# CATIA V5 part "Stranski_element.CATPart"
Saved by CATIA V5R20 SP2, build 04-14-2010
Part number: Stranski_element
Bounding box of the stored display mesh (mm): x -125 to 100, y -20 to 30, z 0 to 2
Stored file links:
  C:\Documents and Settings\Administrator\My Documents\Hobi_dokumenti\CAD_CNC\Clap_CATIA\Stranski_element.CATPart
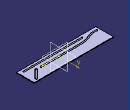
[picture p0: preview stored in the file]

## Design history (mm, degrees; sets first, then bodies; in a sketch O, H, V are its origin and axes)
Body1 (main body)
  Sketch1 on xy-plane, origin (0, 0, 0), H (1, 0, 0), V (0, 1, 0)
    line L1 (-125, 30) -> (100, 30)
    line L2 (100, 30) -> (100, -20)
    line L3 (100, -20) -> (-125, -20)
    line L4 (-125, -20) -> (-125, 30)
    distance V L4 = 125
    length L2 = 50
    distance V L2 = 100
    distance H L3 = 20
    horizontal: L1 H, L3 H
    vertical: L2 V, L4 V
  Pad1: profile Sketch1, direction (0, 0, 1), length 2
  Sketch2 on end face of Pad1, origin (0, 0, 2), H (1, 0, 0), V (0, 1, 0)
    arc A1 centre (87, 23) radius 3 from (89.1213, 20.8787) to (84.8787, 25.1213) ccw
    point P1 (87, 23)
    arc A2 centre (64.321, 0.321) radius 3 from (62.1997, 2.4423) to (66.4423, -1.8003) ccw
    point P2 (64.321, 0.321)
    line L1 (62.1997, 2.4423) -> (84.8787, 25.1213)
    line L2 (89.1213, 20.8787) -> (66.4423, -1.8003)
    line L3 (-80, -10) -> (90, -10)
    line L4 (90, -10) -> (90, -14)
    line L5 (90, -14) -> (-80, -14)
    line L6 (-80, -14) -> (-80, -10)
    reference projected line E1 (100, -20) -> (100, 30) from edge [face of Pad1 from Sketch1.L2 | end face of Pad1]
    reference projected line E2 (-125, -20) -> (100, -20) from edge [face of Pad1 from Sketch1.L3 | end face of Pad1]
    distance P1 V = 87
    distance P1 H = 23
    distance P1 P2 = 32.0729
    radius A1 = 3
    radius A2 = 3
    angle V L1 = 45
    length L5 = 170
    length L4 = 4
    distance E1 L4 = 10
    distance E2 L5 = 6
    tangency: L1 A2, L1 A1, L2 A1, L2 A2
    horizontal: L3 H, L5 H
    vertical: L4 V, L6 V
  Pocket1: profile Sketch2, direction (0, 0, -1), length 2
  Sketch3 on end face of Pad1, origin (0, 0, 2), H (1, 0, 0), V (0, 1, 0)
    spline S1 through (-119.9349, -11.2603) (-98.8623, -10.2752) (-78.9091, -3.4682) (-56.1675, -1.0411) (-45.3865, -1.0411) (-12.8774, -1.0411) (27.9247, -1.0411) (53.9685, -1.0411)
    offsetcurve C1
    construction line L1 (-119.9349, -11.2603) -> (-119.1659, -7.3349)
    point P3 (-119.9349, -11.2603)
    construction line L2 through (-119.9349, -11.2603) direction (-0.9813, 0.1923)
    construction line L3 (53.9685, -1.0411) -> (53.9625, 2.9589)
    point P4 (53.9685, -1.0411)
    construction line L4 through (53.9685, -1.0411) direction (1, 0.0015)
    line L5 (-119.9349, -11.2603) -> (-119.1659, -7.3349)
    point P5 (-119.9349, -11.2603)
    line L6 (53.9685, -1.0411) -> (53.9625, 2.9589)
    point P6 (53.9685, -1.0411)
    point P7 (-119.9349, -11.2603)
    point P8 (53.9685, -1.0411)
    coincidence: P7 P3, P8 P4, P7 P5, P8 P6
    tangency: L2 S1, L4 S1
    perpendicularity: L1 L2, L3 L4
  Pocket2: profile Sketch3, direction (0, 0, -1), length 2
  Fillet1: radius 2, on edge [face of Pocket1 from Sketch2.L5 | face of Pocket1 from Sketch2.L6]; edge [face of Pocket2 from Sketch3.S1 | face of Pocket2 from Sketch3.L5]; edge [face of Pocket1 from Sketch2.L6 | face of Pocket1 from Sketch2.L3]; edge [face of Pocket2 from Sketch3.L5 | face of Pocket2 from Sketch3.C1]; edge [face of Pocket2 from Sketch3.C1 | face of Pocket2 from Sketch3.L6]; edge [face of Pocket1 from Sketch2.L3 | face of Pocket1 from Sketch2.L4]; edge [face of Pocket2 from Sketch3.L6 | face of Pocket2 from Sketch3.S1]; edge [face of Pocket1 from Sketch2.L4 | face of Pocket1 from Sketch2.L5]
  Sketch4 on end face of Pad1, origin (0, 0, 2), H (1, 0, 0), V (0, 1, 0)
    offset curve E1 from edge [end face of Pad1 | face of Pocket2 from Sketch3.C1]
    offset line E2 (88, -12) -> (-78, -12) from edge [end face of Pad1 | face of Pocket1 from Sketch2.L3]
    offset line E3 (87, 23) -> (64.321, 0.321) from edge [end face of Pad1 | face of Pocket1 from Sketch2.L1]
